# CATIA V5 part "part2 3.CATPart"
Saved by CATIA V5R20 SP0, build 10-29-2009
Part number: UFO底座3
Bounding box of the stored display mesh (mm): x -45 to 45, y -45 to 44.964, z -60 to 0
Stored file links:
  C:\Users\16057\Documents\180511420 创意设计\part2 3.CATPart
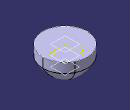
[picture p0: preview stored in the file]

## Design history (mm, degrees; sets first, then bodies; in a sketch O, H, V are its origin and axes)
Body1 (main body)
  Plane1: type Offset, RefPlane xy-plane, Offset 20, reversed
  Plane2: type Offset, RefPlane Plane1, Offset 20, reversed
  Sketch1 on Plane2, origin (0, 0, -40), H (1, 0, 0), V (0, 1, 0)
    circle A1 centre (0, 0) radius 30
    radius A1 = 30
  Sketch2 on Plane1, origin (0, 0, -20), H (1, 0, 0), V (0, 1, 0)
    circle A1 centre (0, 0) radius 45
    radius A1 = 45
  Sketch3 on xy-plane, origin (0, 0, 0), H (1, 0, 0), V (0, 1, 0)
    circle A1 centre (0, 0) radius 45
    radius A1 = 45
  Plane3: type Offset, RefPlane Plane2, Offset 20, reversed
  Sketch4 on Plane3, origin (0, 0, -60), H (1, 0, 0), V (0, 1, 0)
    circle A1 centre (0, 0) radius 0.05
    radius A1 = 0.05
  Loft1: solid, Sections (Sketch4; Sketch1; Sketch2)
  Pad1: profile face of Loft1, direction along Plane1, length 20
